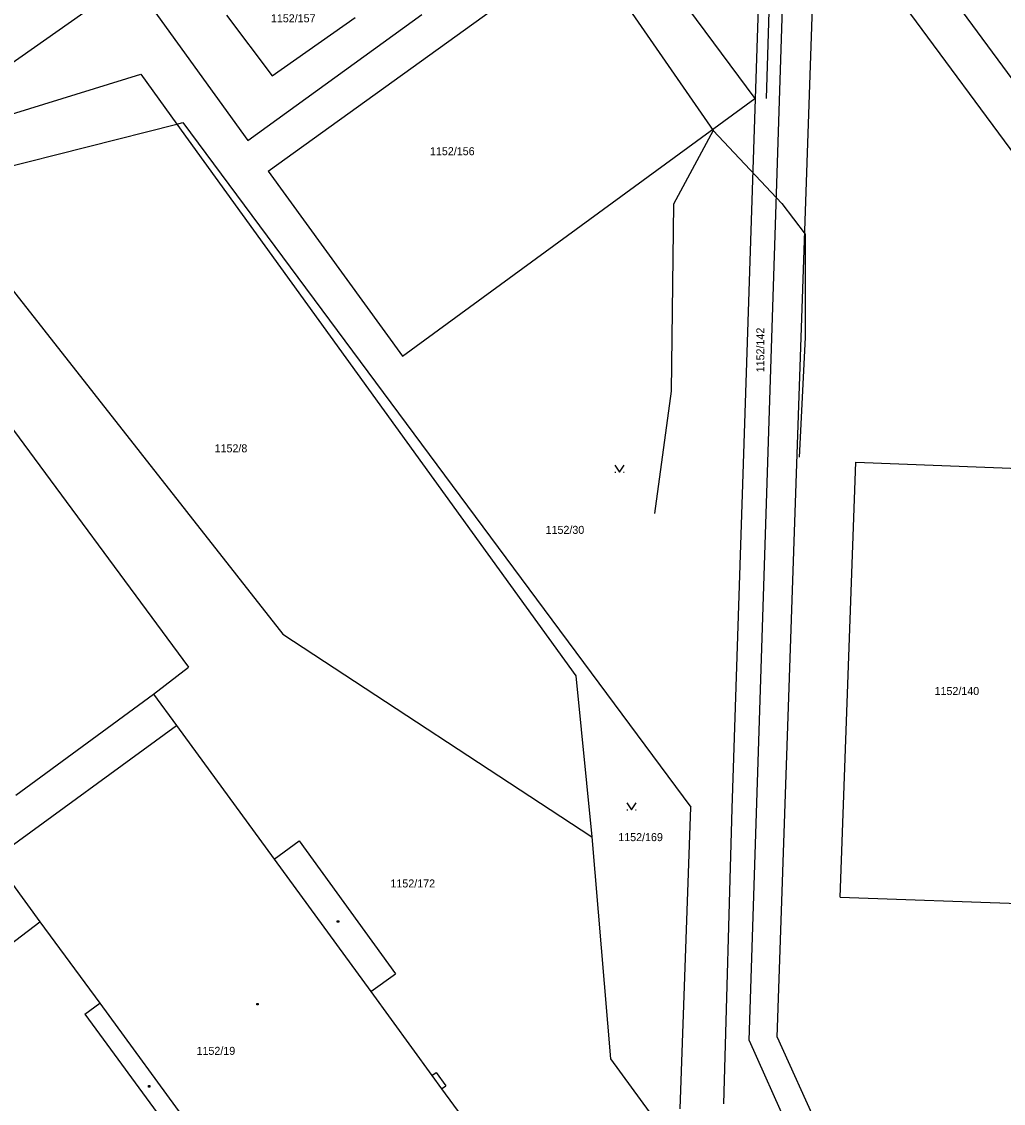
# Model space of a CAD drawing. Extents: x -609709 to -609357, y -1051535 to -1051131.
# Drawn here: x -609637.3 to -609585.1, y -1051388.6 to -1051331.1 of the extents above; entities that cross this region are included whole.
import ezdxf

# ---------------------------------------------------------------- set-up
doc = ezdxf.new("R2010")
doc.units = 0
for name, color, linetype in [('Vrstva 10', 7, 'Continuous'), ('Vrstva 12', 7, 'Continuous'), ('Vrstva 15', 7, 'Continuous')]:
    doc.layers.add(name, color=color, linetype=linetype)

msp = doc.modelspace()

# ---------------------------------------------------------------- linework, layer by layer
at = {"layer": 'Vrstva 10'}
for p, q in [((-609598.65, -1051385.24), (-609596.25, -1051310.74)), ((-609599.55, -1051372.92), (-609597.54, -1051311.69)), ((-609597.16, -1051385.07), (-609595.06, -1051324)), ((-609595.06, -1051324), (-609556.61, -1051376.01)), ((-609624.19, -1051339.08), (-609605.48, -1051325.6)), ((-609605.48, -1051325.6), (-609598.35, -1051335.21)), ((-609589.8, -1051327.23), (-609580.95, -1051339.28)), ((-609643.62, -1051337.41), (-609631.47, -1051328.87)), ((-609631.47, -1051328.87), (-609625.28, -1051337.44)), ((-609626.4, -1051330.8), (-609623.99, -1051334.02)), ((-609625.28, -1051337.44), (-609616.03, -1051330.75)), ((-609623.99, -1051334.02), (-609619.58, -1051330.92)), ((-609683, -1051349.98), (-609630.95, -1051333.93)), ((-609630.95, -1051333.93), (-609629.04, -1051336.58)), ((-609617.06, -1051348.9), (-609598.35, -1051335.21)), ((-609682.96, -1051350.15), (-609629.04, -1051336.58)), ((-609629.04, -1051336.58), (-609628.73, -1051336.5)), ((-609629.04, -1051336.58), (-609607.86, -1051365.88)), ((-609628.73, -1051336.5), (-609601.74, -1051372.86)), ((-609624.19, -1051339.08), (-609617.06, -1051348.9)), ((-609639.21, -1051343.57), (-609623.41, -1051363.66)), ((-609641.82, -1051347.3), (-609628.43, -1051365.42)), ((-609605.78, -1051354.695), (-609605.53, -1051355.07)), ((-609605.53, -1051355.07), (-609605.28, -1051354.695)), ((-609593.82, -1051377.63), (-609592.98, -1051354.53)), ((-609592.98, -1051354.53), (-609580.88, -1051355.01)), ((-609605.78, -1051355.07), (-609605.73, -1051355.07)), ((-609605.33, -1051355.07), (-609605.28, -1051355.07)), ((-609623.41, -1051363.66), (-609607, -1051374.44)), ((-609630.28, -1051366.85), (-609628.43, -1051365.42)), ((-609607.86, -1051365.88), (-609607, -1051374.44)), ((-609637.59, -1051372.21), (-609630.28, -1051366.85)), ((-609630.28, -1051366.85), (-609629.07, -1051368.51)), ((-609638.77, -1051375.59), (-609629.07, -1051368.51)), ((-609629.07, -1051368.51), (-609623.88, -1051375.61)), ((-609605.14, -1051372.625), (-609604.89, -1051373)), ((-609605.14, -1051373), (-609605.09, -1051373)), ((-609604.89, -1051373), (-609604.64, -1051372.625)), ((-609604.69, -1051373), (-609604.64, -1051373)), ((-609602.32, -1051388.88), (-609601.74, -1051372.86)), ((-609600, -1051388.61), (-609599.55, -1051372.92)), ((-609623.88, -1051375.61), (-609622.55, -1051374.64)), ((-609622.55, -1051374.64), (-609617.44, -1051381.71)), ((-609607, -1051374.44), (-609606.02, -1051386.23)), ((-609638.77, -1051375.59), (-609636.32, -1051378.94)), ((-609623.88, -1051375.61), (-609618.74, -1051382.65)), ((-609593.82, -1051377.63), (-609581.73, -1051378.07)), ((-609620.525, -1051378.885), (-609620.45, -1051378.885)), ((-609620.525, -1051378.96), (-609620.525, -1051378.885)), ((-609620.45, -1051378.885), (-609620.45, -1051378.96)), ((-609653.49, -1051392.02), (-609636.32, -1051378.94)), ((-609636.32, -1051378.94), (-609633.14, -1051383.27)), ((-609620.45, -1051378.96), (-609620.525, -1051378.96)), ((-609618.74, -1051382.65), (-609617.44, -1051381.71)), ((-609618.74, -1051382.65), (-609615.5, -1051387.1)), ((-609633.93, -1051383.85), (-609633.14, -1051383.27)), ((-609633.14, -1051383.27), (-609627.36, -1051391.16)), ((-609624.795, -1051383.275), (-609624.72, -1051383.275)), ((-609624.795, -1051383.35), (-609624.795, -1051383.275)), ((-609624.72, -1051383.35), (-609624.795, -1051383.35)), ((-609624.72, -1051383.275), (-609624.72, -1051383.35)), ((-609633.93, -1051383.85), (-609628.14, -1051391.73)), ((-609598.65, -1051385.24), (-609592.42, -1051399.18)), ((-609597.16, -1051385.07), (-609590.06, -1051400.76)), ((-609606.02, -1051386.23), (-609588.77, -1051409.69)), ((-609615.5, -1051387.1), (-609615.28, -1051386.94)), ((-609615.28, -1051386.94), (-609614.76, -1051387.65)), ((-609615.5, -1051387.1), (-609614.98, -1051387.81)), ((-609630.555, -1051387.645), (-609630.48, -1051387.645)), ((-609630.555, -1051387.72), (-609630.555, -1051387.645)), ((-609630.48, -1051387.72), (-609630.555, -1051387.72)), ((-609630.48, -1051387.645), (-609630.48, -1051387.72)), ((-609614.98, -1051387.81), (-609614.76, -1051387.65)), ((-609614.98, -1051387.81), (-609612.03, -1051391.85))]:
    msp.add_line(p, q, dxfattribs=at)
at = {"layer": 'Vrstva 12'}
for points in [[(-609612.018, -1051322.176), (-609611.07, -1051324.6), (-609609.16, -1051326.39), (-609607.41, -1051327.01), (-609600.56, -1051336.92), (-609602.67, -1051340.83), (-609602.79, -1051350.77), (-609603.67, -1051357.26)], [(-609600.56, -1051336.92), (-609596.91, -1051340.8), (-609595.68, -1051342.42), (-609595.67, -1051347.91), (-609595.99, -1051354.27)]]:
    msp.add_lwpolyline(points, dxfattribs=at)
at = {"layer": 'Vrstva 15'}
msp.add_lwpolyline([(-609588.82, -1051311.77), (-609594.6, -1051316.05), (-609596.4, -1051317.24), (-609597.23, -1051322.04), (-609597.58, -1051330.03), (-609597.74, -1051335.22)], dxfattribs=at)

# ---------------------------------------------------------------- texts
at = {"layer": 'Vrstva 10'}
for s, p in [('1152/157', (-609624.05, -1051331.17)), ('1152/156', (-609615.6, -1051338.23)), ('1152/8', (-609627.04, -1051354.01)), ('1152/30', (-609609.46, -1051358.34)), ('1152/140', (-609588.8, -1051366.9)), ('1152/169', (-609605.6, -1051374.66)), ('1152/172', (-609617.7, -1051377.12)), ('1152/19', (-609628, -1051386.01))]:
    msp.add_text(s, height=0.425, dxfattribs=at).set_placement(p)
msp.add_text('1152/142', height=0.425, rotation=90, dxfattribs=at).set_placement((-609597.84, -1051349.76))

doc.saveas('drawing.dxf')
